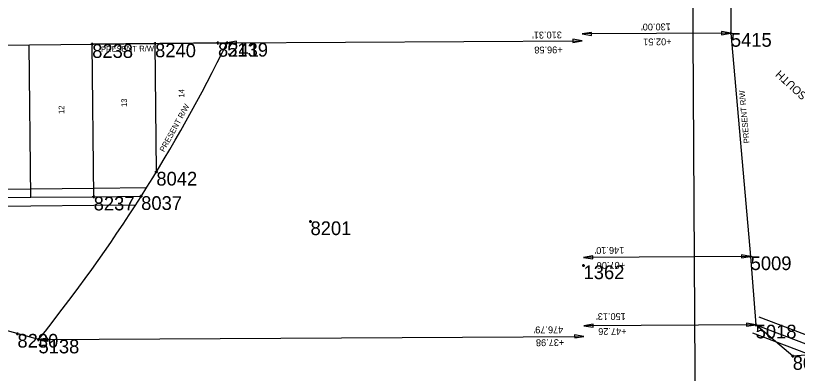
# Model space of a CAD drawing. Extents: x 2145146 to 2158053, y 137507 to 150829.
# Drawn here: x 2150322 to 2151005, y 143925 to 144238 of the extents above; entities that cross this region are included whole.
import ezdxf

# ---------------------------------------------------------------- set-up
doc = ezdxf.new("R2010")
doc.units = 0
for name, color, linetype in [('ALIGN_Cogo Points', 7, 'Continuous'), ('ALIGN_ROW Dimension', 7, 'Continuous'), ('ALIGN_ROW Line', 7, 'Continuous'), ('ALIGN_ROW Text', 7, 'Continuous'), ('PLSS_Block Line', 7, 'Continuous'), ('PLSS_Easement', 7, 'Continuous'), ('PLSS_Lot Line', 7, 'Continuous'), ('PLSS_Property Line', 7, 'Continuous'), ('PLSS_Section Line', 7, 'Continuous'), ('PLSS_Text', 7, 'Continuous'), ('PLSS_Text_TURNED OFF', 7, 'Continuous')]:
    doc.layers.add(name, color=color, linetype=linetype)

# ---------------------------------------------------------------- blocks, each defined once
blk = doc.blocks.new('Arrowhd')
at = {"layer": 'PLSS_Property Line'}
blk.add_lwpolyline([(0.125, -0.021), (0.125, 0.021), (0, 0)], close=True, dxfattribs=at)

msp = doc.modelspace()

# ---------------------------------------------------------------- linework, layer by layer
at = {"layer": 'ALIGN_Cogo Points'}
for points in [[(2150947.31, 144222.48), (2150947.31, 144223.68), (2150947.31, 144222.48), (2150946.11, 144222.48), (2150947.31, 144222.48), (2150947.31, 144221.28), (2150947.31, 144222.48), (2150948.51, 144222.48)], [(2150389.07, 144212.75), (2150389.07, 144213.95), (2150389.07, 144212.75), (2150387.87, 144212.75), (2150389.07, 144212.75), (2150389.07, 144211.55), (2150389.07, 144212.75), (2150390.27, 144212.75)], [(2150444.05, 144213.29), (2150444.05, 144214.49), (2150444.05, 144213.29), (2150442.85, 144213.29), (2150444.05, 144213.29), (2150444.05, 144212.09), (2150444.05, 144213.29), (2150445.25, 144213.29)], [(2150499.03, 144213.82), (2150499.03, 144215.02), (2150499.03, 144213.82), (2150497.83, 144213.82), (2150499.03, 144213.82), (2150499.03, 144212.62), (2150499.03, 144213.82), (2150500.23, 144213.82)], [(2150507.04, 144213.9), (2150507.04, 144215.1), (2150507.04, 144213.9), (2150505.84, 144213.9), (2150507.04, 144213.9), (2150507.04, 144212.7), (2150507.04, 144213.9), (2150508.24, 144213.9)], [(2150445.15, 144101.08), (2150445.15, 144102.28), (2150445.15, 144101.08), (2150443.95, 144101.08), (2150445.15, 144101.08), (2150445.15, 144099.88), (2150445.15, 144101.08), (2150446.35, 144101.08)], [(2150390.38, 144079.36), (2150390.38, 144080.56), (2150390.38, 144079.36), (2150389.18, 144079.36), (2150390.38, 144079.36), (2150390.38, 144078.16), (2150390.38, 144079.36), (2150391.58, 144079.36)], [(2150431.88, 144079.76), (2150431.88, 144080.96), (2150431.88, 144079.76), (2150430.68, 144079.76), (2150431.88, 144079.76), (2150431.88, 144078.56), (2150431.88, 144079.76), (2150433.08, 144079.76)], [(2150579.91, 144057.75), (2150579.91, 144058.95), (2150579.91, 144057.75), (2150578.71, 144057.75), (2150579.91, 144057.75), (2150579.91, 144056.55), (2150579.91, 144057.75), (2150581.11, 144057.75)], [(2150964.59, 144027.13), (2150964.59, 144028.33), (2150964.59, 144027.13), (2150963.39, 144027.13), (2150964.59, 144027.13), (2150964.59, 144025.93), (2150964.59, 144027.13), (2150965.79, 144027.13)], [(2150818.53, 144019.2), (2150818.53, 144020.4), (2150818.53, 144019.2), (2150817.33, 144019.2), (2150818.53, 144019.2), (2150818.53, 144018), (2150818.53, 144019.2), (2150819.73, 144019.2)], [(2150968.98, 143967.36), (2150968.98, 143968.56), (2150968.98, 143967.36), (2150967.78, 143967.36), (2150968.98, 143967.36), (2150968.98, 143966.16), (2150968.98, 143967.36), (2150970.18, 143967.36)], [(2150323.73, 143959.34), (2150323.73, 143960.54), (2150323.73, 143959.34), (2150322.53, 143959.34), (2150323.73, 143959.34), (2150323.73, 143958.14), (2150323.73, 143959.34), (2150324.93, 143959.34)], [(2150342.12, 143954.31), (2150342.12, 143955.51), (2150342.12, 143954.31), (2150340.92, 143954.31), (2150342.12, 143954.31), (2150342.12, 143953.11), (2150342.12, 143954.31), (2150343.32, 143954.31)], [(2151001.37, 143939.89), (2151001.37, 143941.09), (2151001.37, 143939.89), (2151000.17, 143939.89), (2151001.37, 143939.89), (2151001.37, 143938.69), (2151001.37, 143939.89), (2151002.57, 143939.89)]]:
    msp.add_lwpolyline(points, dxfattribs=at)
at = {"layer": 'ALIGN_ROW Dimension'}
for points in [[(2150947.31, 144222.48), (2150817.32, 144221.7)], [(2150507.04, 144213.9), (2150817.35, 144215.77)], [(2150964.59, 144027.13), (2150818.49, 144026.25)], [(2150968.98, 143967.36), (2150818.85, 143966.46)], [(2150342.12, 143954.31), (2150818.91, 143957.17)]]:
    msp.add_lwpolyline(points, dxfattribs=at)
at = {"layer": 'ALIGN_ROW Line'}
for points in [[(2150966.92, 144832.96), (2150967.01, 144819.7), (2150963.34, 144732.92), (2150962.14, 144594.9), (2150960.63, 144422.47), (2150956.11, 144422.54), (2150956.27, 144395.54), (2150946.27, 144395.48), (2150947.31, 144222.48), (2150964.59, 144027.13), (2150968.98, 143967.36)], [(2150507.04, 144213.9), (2150389.07, 144212.75)]]:
    msp.add_lwpolyline(points, dxfattribs=at)
for centre, radius, start, end in [((2149252.26, 144828.89), 1397.39, 321.25418, 333.89003), ((2150166.55, 143377.48), 602.96, 73.07114, 82.92018)]:
    msp.add_arc(centre, radius, start, end, dxfattribs=at)
at = {"layer": 'PLSS_Block Line'}
msp.add_lwpolyline([(2150224.14, 144211.13), (2150444.05, 144213.29), (2150507.04, 144213.9)], dxfattribs=at)
at = {"layer": 'PLSS_Easement'}
for points in [[(2150966.29, 143960.36), (2151023.92, 143938.26), (2151215.08, 143953.41), (2151215.03, 144214.86), (2151144.43, 144295.52), (2151144.45, 144636.46), (2150962.64, 144635.49)], [(2150968.98, 143967.36), (2151025.02, 143945.87), (2151207.58, 143960.33), (2151207.53, 144212.04), (2151136.93, 144292.7), (2151136.95, 144628.92), (2150962.68, 144627.99)], [(2150971.66, 143974.36), (2151026.12, 143953.49), (2151200.08, 143967.26), (2151200.03, 144209.22), (2151129.43, 144289.88), (2151129.45, 144621.38), (2150962.72, 144620.49)], [(2150035.91, 144096.82), (2150225.86, 144086.18), (2150240.04, 144085.39), (2150280.35, 144085.78), (2150335.33, 144086.32), (2150390.31, 144086.86), (2150436.64, 144087.31)], [(2150035.07, 144081.85), (2150225.02, 144071.2), (2150239.69, 144070.38), (2150280.5, 144070.78), (2150335.48, 144071.32), (2150390.45, 144071.86), (2150427.05, 144072.21)]]:
    msp.add_lwpolyline(points, dxfattribs=at)
at = {"layer": 'PLSS_Lot Line'}
for points in [[(2150335.4, 144078.78), (2150334.1, 144212.17)], [(2150390.38, 144079.36), (2150389.07, 144212.75)], [(2150445.17, 144101.12), (2150444.07, 144213.29)], [(2150154.64, 144082.66), (2150225.44, 144078.69), (2150239.87, 144077.88), (2150280.43, 144078.28), (2150335.4, 144078.82), (2150390.38, 144079.36), (2150431.88, 144079.76)]]:
    msp.add_lwpolyline(points, dxfattribs=at)
at = {"layer": 'PLSS_Property Line'}
msp.add_lwpolyline([(2151299.95, 143963.89), (2151299.95, 143963.89), (2151001.37, 143939.89), (2150968.98, 143967.36)], dxfattribs=at)
at = {"layer": 'PLSS_Section Line'}
msp.add_lwpolyline([(2150921.68, 142997.28), (2150905.82, 145638.98)], dxfattribs=at)

# ---------------------------------------------------------------- block references
at = {"layer": 'ALIGN_ROW Dimension'}
for p, xscale, yscale, rotation in [((2150947.31, 144222.48), 65.00000000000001, 64.99999999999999, -179.65177652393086), ((2150817.35, 144215.77), 65.00000000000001, 64.99999999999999, -179.65177652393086), ((2150817.3, 144221.7), 65, 65, 0.2668843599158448), ((2150507.03, 144213.91), 65, 65, 0.2668843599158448), ((2150818.48, 144026.25), 65, 65, 0.2668843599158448), ((2150964.59, 144027.13), 65.00000000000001, 64.99999999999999, -179.65177652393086), ((2150818.84, 143966.46), 65, 65, 0.2668843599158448), ((2150968.98, 143967.36), 65.00000000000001, 64.99999999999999, -179.65177652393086), ((2150818.91, 143957.17), 65.00000000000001, 64.99999999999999, -179.65177652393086), ((2150342.18, 143954.31), 65, 65, 0.2668843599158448)]:
    msp.add_blockref('Arrowhd', p, dxfattribs=dict(at, xscale=xscale, yscale=yscale, rotation=rotation))

# ---------------------------------------------------------------- texts
at = {"layer": 'ALIGN_Cogo Points'}
for s, p in [('5415', (2150947.31, 144210.48)), ('8238', (2150389.07, 144200.75)), ('8240', (2150444.05, 144201.29)), ('8241', (2150499.03, 144201.82)), ('5139', (2150507.04, 144201.9)), ('8042', (2150445.15, 144089.08)), ('8237', (2150390.38, 144067.36)), ('8037', (2150431.88, 144067.76)), ('8201', (2150579.91, 144045.75)), ('5009', (2150964.59, 144015.13)), ('1362', (2150818.53, 144007.2)), ('5018', (2150968.98, 143955.36)), ('8230', (2150323.73, 143947.34)), ('5138', (2150342.12, 143942.31)), ('8048', (2151001.37, 143927.89))]:
    msp.add_text(s, height=12, dxfattribs=at).set_placement(p)
at = {"layer": 'ALIGN_ROW Dimension'}
for s, p in [("130.00'", (2150894.79, 144230.91)), ("310.31'", (2150799.58, 144223.83)), ('+02.51', (2150895.43, 144217.86)), ('+96.58', (2150800.23, 144210.78)), ("146.10'", (2150854.16, 144035.38)), ('+07.06', (2150854.81, 144022.33)), ("150.13'", (2150855.48, 143977.55)), ("476.79'", (2150800.84, 143965.92)), ('+47.26', (2150856.12, 143964.5)), ('+37.98', (2150801.67, 143954.72))]:
    msp.add_text(s, height=6, rotation=180.3718, dxfattribs=at).set_placement(p)
at = {"layer": 'ALIGN_ROW Text'}
for rotation, p in [(0.58961, (2150396.75, 144205.98)), (95.21232, (2150963.59, 144126.32)), (61.30213, (2150452, 144117.96))]:
    msp.add_text('PRESENT R/W', height=5, rotation=rotation, dxfattribs=at).set_placement(p)
at = {"layer": 'PLSS_Text'}
for s, p in [('14', (2150469.7, 144166)), ('13', (2150419.52, 144157.81)), ('12', (2150364.72, 144151.66))]:
    msp.add_text(s, height=5, rotation=90, dxfattribs=at).set_placement(p)
at = {"layer": 'PLSS_Text_TURNED OFF'}
msp.add_text('CROSSROADS SOUTH', height=7, rotation=137.49751, dxfattribs=at).set_placement((2151065.49, 144121.66))

doc.saveas('drawing.dxf')
